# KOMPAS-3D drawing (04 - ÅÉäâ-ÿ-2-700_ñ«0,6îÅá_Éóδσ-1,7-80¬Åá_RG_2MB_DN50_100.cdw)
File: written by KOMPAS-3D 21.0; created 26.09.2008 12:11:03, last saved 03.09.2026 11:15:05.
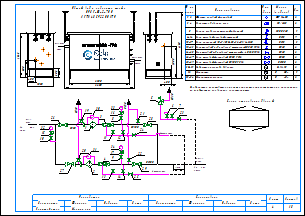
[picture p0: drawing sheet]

Sheets 1-2: A3, landscape

Document properties: Наименование: Макро:21; Автор: RaskoAdmin; Форматы листов документа: 2xA3; Полное имя файла: \\UR38nt01\Departments\КТО\КБ ПУРДГ\Заявки\Прайс-лист на типовые шкафы ГРПШ\ПРДГ_стандарт_20_03_2026\ПРДГ с RG_2MB\ПРДГ-Ш-2-700_до0,6МПа_Рвых-1,7-80кПа_RG_2MB_DN50_100.cdw

Title block, sheet 1: Наименование: Пункт учета газа / ПУГ-Ш-400-Р / ЛГТИ.485922.001ТУ; designation: ЛГТИ.03.4411141; sheet number: 1; Количество листов документа: 2; organisation: ООО "ЭЛЬСТЕР Газэлектроника"; Форматы листов документа: A3; stored path: C:\Рабочие документы\Компас\ПУГ\Схема.cdw; Разработал: Устинов; Проверил: Кошкин; Утвердил: Кошкин
Title block, sheet 2: sheet number: 2; stored path: D:\Рабочие документы\Заявки\ПУРДГ\ПУРДГ-ШУЭО-2-100-Р 4411220.cdw; designation, second copy: ЛГТИ.03.4411141-

Views: Вид 1, Вид 2
Referenced files: wcvoit.frw
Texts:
  Normal
  Вход
  газа
  PDI
  Выход
  Р=     кПа
  DN100
  DN50
  DN20
  Импульс DN20
  ≥5DN
  HYSWLongFangSong
  № на
  схеме
  Усл.
  обозн.
  Марка
  (модель)
  Кол.
  Фильтр газовый фланцевый
  ФГ 16-50
  Регулятор давления газа
  RG/2MB
  Клапан предохранительный сбросной
  КПС DN20
  Кран шаровой газовый латунный
  DN15
  Кран кнопочный VE-РАСКО-НЗ-1,6-G1/2-М20
  Кран шаровой "под приварку" штуцерный DN20 PN16
  Кран шаровой "под приварку" штуцерный п/п DN20 PN16
  Кран шаровой фланцевый DN50 PN16
  Кран шаровой фланцевый DN100 PN16
  Индикатор перепада давления
  Delta 15
  Манометр
  Манометр-напоромер
  0...     МПа
  0...     кПа
  Общий вид и габариты шкафа
  ПРДГ-Ш-2-700
  Выход газа
  Вход газа
  Р=        МПа
  logo-rasko-ge.png
  Схема открывания дверей
  Предприятие изготовитель может заменять комплектующие на аналогичные,
  не ухудшающие заявленных характеристик.
  Должность
  Конструктор
  Фамилия
  Подпись
  Дата
  Согласовано
  Максимкин
  Лист
  Листов
  POLYLINE_STYLE_0.18_RGB_0_0_0
  POLYLINE_STYLE_0.50_RGB_0_0_0
  POLYLINE_STYLE_0.34_RGB_0_0_0
  PHANTOM_RGB_0_0_0_SC_1_THICK_0.18
  K5LT_THIN_RGB_0_0_0_THICK_0.18
  K5LT32769_RGB_0_0_0_THICK_0.18
  K5LT12_RGB_0_0_0_SC_1_THICK_0.18
  K5LT_DASHED_RGB_0_0_0_SC_1_THICK_0.18
  ACISOTGL_RGB_0_0_0_SC_0.8_THICK_0.25
  CONTINUOUS_RGB_0_127_31_THICK_0.3
  CONTINUOUS_RGB_0_0_255_THICK_0.35
  CONTINUOUS_RGB_255_0_0_THICK_0.35
  POLYLINE_STYLE_0.25_RGB_0_0_0
  CONTINUOUS_RGB_0_0_0_THICK_0.5
  POLYLINE_STYLE_0.35_RGB_0_0_255
  CONTINUOUS_RGB_0_0_0_THICK_0.4
  CONTINUOUS_RGB_0_0_0_THICK_0.35
  Без оформления
Dimensions and other numbers on the sheet: 1; 2; 3; 4; 5; 10; 27; 28; 29; 23; 8; 12; 19; 20; 21; 22; 25; 24; 30; 31; 15; 16; 26; 6; 7; 11; 14; 13; 33; 1, 2; 3, 4; 6-14; 9; 15-17; 18-23; 24-25; 26-27; 28-29; 30-31; 32; 33-34; 400; 1050; 500; 305; 2300; 1565; 2600; 17; 34; 1000; 4130; 18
